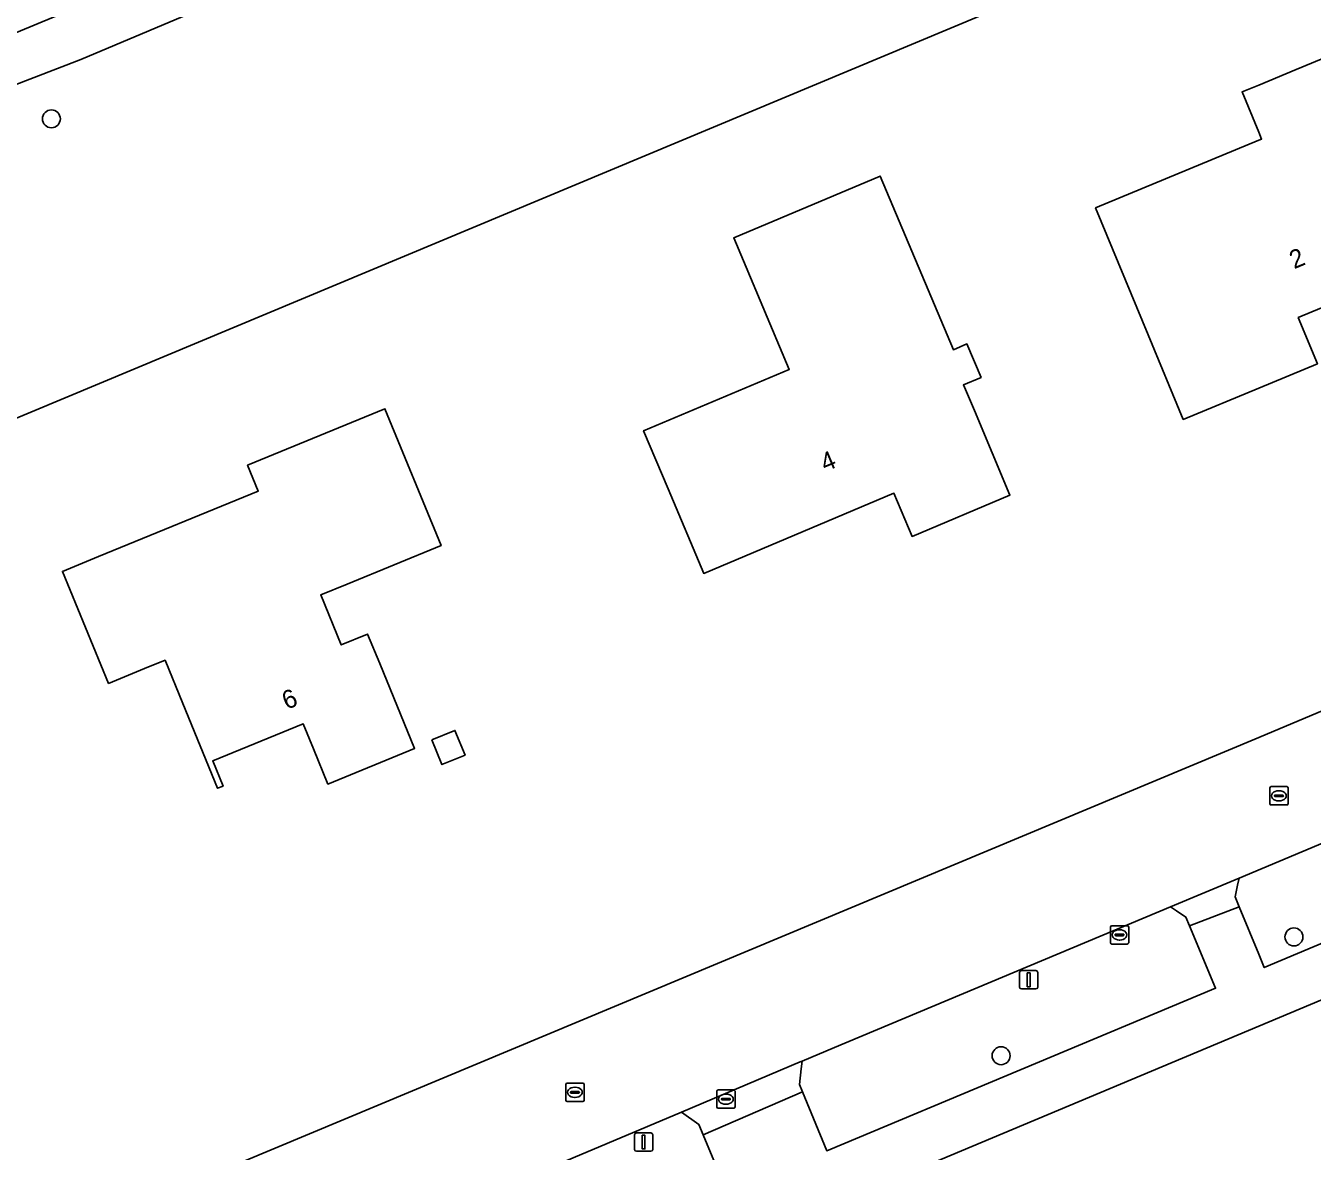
# Model space of a CAD drawing. Extents: x 162417 to 163722, y 384268 to 385417.
# Drawn here: x 163432.7 to 163502.9, y 385024.2 to 385085.6 of the extents above; entities that cross this region are included whole.
import ezdxf

# ---------------------------------------------------------------- set-up
doc = ezdxf.new("R2010")
doc.units = 0
for name, color, linetype in [('IMGEO_Berm_groen', 7, 'Continuous'), ('IMGEO_Boom', 7, 'Continuous'), ('IMGEO_Erf', 7, 'Continuous'), ('IMGEO_Groenvoorziening', 7, 'Continuous'), ('IMGEO_Kolk', 7, 'Continuous'), ('IMGEO_Lichtmast', 7, 'Continuous'), ('IMGEO_Loofbos', 7, 'Continuous'), ('IMGEO_Pand', 7, 'Continuous'), ('IMGEO_Pand_nummerreeks', 7, 'Continuous'), ('IMGEO_Rijbaan_lokaal_gesloten', 7, 'Continuous'), ('IMGEO_Rioolput', 7, 'Continuous'), ('IMGEO_Voetpad_halfverhard', 7, 'Continuous'), ('IMGEO_Voetpad_open', 7, 'Continuous')]:
    doc.layers.add(name, color=color, linetype=linetype)

msp = doc.modelspace()

# ---------------------------------------------------------------- linework, layer by layer
at = {"layer": 'IMGEO_Berm_groen'}
msp.add_lwpolyline([(163529.399, 385051.967), (163526.498, 385050.73), (163505.769, 385042.017), (163498.926, 385039.152), (163498.844, 385038.762), (163498.711, 385038.132), (163498.937, 385037.584), (163500, 385035.007), (163500.305, 385034.267), (163533.125, 385048.062)], dxfattribs=at)
for points in [[(163497.646, 385033.141), (163496.228, 385036.548), (163496.03, 385037.025), (163495.516, 385037.371), (163495.193, 385037.589), (163476.854, 385029.911), (163475.087, 385029.166), (163475.042, 385028.747), (163474.948, 385027.895), (163475.114, 385027.491), (163476.433, 385024.272)], [(163470.993, 385022.003), (163469.69, 385025.15), (163469.456, 385025.715), (163468.504, 385026.389), (163448.57, 385017.982), (163448.438, 385017.701), (163448.097, 385016.974), (163448.318, 385016.446), (163449.689, 385013.164)]]:
    msp.add_lwpolyline(points, close=True, dxfattribs=at)
at = {"layer": 'IMGEO_Boom'}
for centre in [(163434.132, 385080.566), (163501.923, 385035.94), (163485.947, 385029.459)]:
    msp.add_circle(centre, 0.489, dxfattribs=at)
at = {"layer": 'IMGEO_Erf'}
for points in [[(163526.981, 385058.237), (163524.402, 385063.53), (163507.868, 385095.856), (163500, 385092.556), (163419.878, 385059.084), (163371.144, 385038.583), (163343.981, 385026.826), (163354.406, 385000), (163357.745, 384991.405), (163359.186, 384987.697), (163387.545, 384999.704), (163388.243, 385000), (163425.932, 385015.904), (163500, 385046.827), (163524.917, 385057.312)], [(163500, 385082.41), (163502.045, 385083.258), (163506.663, 385085.173), (163511.47, 385073.585), (163502.16, 385069.723), (163503.203, 385067.206), (163500, 385065.878), (163495.882, 385064.17), (163493.966, 385068.789), (163491.098, 385075.704), (163500, 385079.397), (163500.156, 385079.461), (163500, 385079.838), (163499.09, 385082.032)], [(163467.782, 385060.378), (163466.445, 385063.55), (163474.386, 385066.897), (163471.362, 385074.072), (163479.351, 385077.439), (163483.342, 385067.971), (163484.082, 385068.283), (163484.851, 385066.459), (163483.894, 385066.055), (163484.488, 385064.647), (163486.43, 385060.039), (163481.092, 385057.789), (163480.099, 385060.143), (163469.725, 385055.77)], [(163450.264, 385055.186), (163448.83, 385054.597), (163449.95, 385051.868), (163451.384, 385052.457), (163452.045, 385050.847), (163453.944, 385046.221), (163449.215, 385044.28), (163448.429, 385046.195), (163447.867, 385047.564), (163442.937, 385045.541), (163443.499, 385044.172), (163443.203, 385044.05), (163441.304, 385048.676), (163440.337, 385051.032), (163439.221, 385050.574), (163437.248, 385049.764), (163434.737, 385055.88), (163436.71, 385056.69), (163445.416, 385060.263), (163444.837, 385061.673), (163452.327, 385064.748), (163455.389, 385057.29)], [(163454.889, 385046.683), (163456.147, 385047.2), (163456.699, 385045.856), (163455.441, 385045.34)]]:
    msp.add_lwpolyline(points, close=True, dxfattribs=at)
msp.add_lwpolyline([(163571.782, 384971.962), (163557.559, 385000), (163534.443, 385045.503), (163500, 385031.078), (163425.859, 385000), (163365.371, 384974.629), (163363.507, 384973.847), (163366.161, 384967.778), (163366.55, 384967.171), (163368.242, 384964.531)], dxfattribs=at)
at = {"layer": 'IMGEO_Groenvoorziening'}
msp.add_lwpolyline([(163481.985, 385145.032), (163480.053, 385147.889), (163478.195, 385150.521), (163474.918, 385154.813), (163471.459, 385158.99), (163429.736, 385126.498), (163414.218, 385078.468), (163428.256, 385083.644), (163444.192, 385090.257), (163456.158, 385095.426)], close=True, dxfattribs=at)
at = {"layer": 'IMGEO_Kolk'}
for p, q in [((163491.906, 385035.624), (163491.906, 385036.476)), ((163491.981, 385036.55), (163492.833, 385036.55)), ((163492.208, 385036.093), (163492.606, 385036.093)), ((163492.394, 385036.33), (163492.419, 385036.33)), ((163492.907, 385036.476), (163492.907, 385035.624)), ((163492.833, 385035.55), (163491.981, 385035.55)), ((163492.165, 385036.044), (163492.165, 385036.056)), ((163492.603, 385036.007), (163492.205, 385036.007)), ((163492.417, 385035.77), (163492.392, 385035.77)), ((163492.649, 385036.056), (163492.649, 385036.044)), ((163470.431, 385026.665), (163470.431, 385027.517)), ((163470.506, 385027.591), (163471.358, 385027.591)), ((163470.69, 385027.085), (163470.69, 385027.097)), ((163471.128, 385027.048), (163470.73, 385027.048)), ((163470.733, 385027.134), (163471.131, 385027.134)), ((163470.919, 385027.371), (163470.944, 385027.371)), ((163471.174, 385027.097), (163471.174, 385027.085)), ((163471.432, 385027.517), (163471.432, 385026.665)), ((163471.358, 385026.591), (163470.506, 385026.591)), ((163470.942, 385026.811), (163470.917, 385026.811))]:
    msp.add_line(p, q, dxfattribs=at)
for points in [[(163491.906, 385035.624), (163491.906, 385036.476)], [(163491.981, 385036.55), (163492.833, 385036.55)], [(163492.907, 385036.476), (163492.907, 385035.624)], [(163492.833, 385035.55), (163491.981, 385035.55)], [(163470.431, 385026.665), (163470.431, 385027.517)], [(163470.506, 385027.591), (163471.358, 385027.591)], [(163471.432, 385027.517), (163471.432, 385026.665)], [(163471.358, 385026.591), (163470.506, 385026.591)]]:
    msp.add_lwpolyline(points, dxfattribs=at)
for centre, radius, start, end in [((163491.983, 385036.474), 0.0765, 91.55205, 178.44795), ((163491.983, 385036.474), 0.0765, 91.55205, 178.44795), ((163492.205, 385036.053), 0.0403, 85.87752, 175.75265), ((163492.61, 385036.055), 0.0386, 1.73085, 96.63898), ((163492.831, 385036.474), 0.0765, 1.55205, 88.44795), ((163492.831, 385036.474), 0.0765, 1.55205, 88.44795), ((163491.983, 385035.626), 0.0765, 181.55205, 268.44795), ((163491.983, 385035.626), 0.0765, 181.55205, 268.44795), ((163492.202, 385036.043), 0.0366, 178.93798, 274.71019), ((163492.606, 385036.05), 0.043, 264.86636, 352.45326), ((163492.831, 385035.626), 0.0765, 271.55205, 358.44795), ((163492.831, 385035.626), 0.0765, 271.55205, 358.44795), ((163470.508, 385027.515), 0.0765, 91.55205, 178.44795), ((163470.508, 385027.515), 0.0765, 91.55205, 178.44795), ((163470.73, 385027.094), 0.0403, 85.87752, 175.75265), ((163470.727, 385027.084), 0.0366, 178.93798, 274.71019), ((163471.131, 385027.091), 0.043, 264.86636, 352.45326), ((163471.135, 385027.096), 0.0386, 1.73085, 96.63898), ((163471.356, 385027.515), 0.0765, 1.55205, 88.44795), ((163471.356, 385027.515), 0.0765, 1.55205, 88.44795), ((163470.508, 385026.667), 0.0765, 181.55205, 268.44795), ((163470.508, 385026.667), 0.0765, 181.55205, 268.44795), ((163471.356, 385026.667), 0.0765, 271.55205, 358.44795), ((163471.356, 385026.667), 0.0765, 271.55205, 358.44795)]:
    msp.add_arc(centre, radius, start, end, dxfattribs=at)
for centre, major_axis, ratio, start_param, end_param in [((163492.393, 385036.05), (-0.387, 0.002), 0.722429, 4.712389, 7.853982), ((163492.418, 385036.05), (-0.39, 0.002), 0.717154, 1.570796, 4.712389), ((163470.918, 385027.091), (-0.387, 0.002), 0.722429, 4.712389, 7.853982), ((163470.943, 385027.091), (-0.39, 0.002), 0.717154, 1.570796, 4.712389)]:
    msp.add_ellipse(centre, major_axis=major_axis, ratio=ratio, start_param=start_param, end_param=end_param, dxfattribs=at)
at = {"layer": 'IMGEO_Lichtmast'}
for p, q in [((163486.955, 385033.2), (163486.955, 385034)), ((163486.955, 385034), (163486.955, 385033.2)), ((163487.055, 385034.1), (163487.845, 385034.1)), ((163487.845, 385034.1), (163487.055, 385034.1)), ((163487.945, 385034), (163487.945, 385033.2)), ((163487.945, 385033.2), (163487.945, 385034)), ((163487.845, 385033.1), (163487.055, 385033.1)), ((163487.055, 385033.1), (163487.845, 385033.1)), ((163465.947, 385024.347), (163465.947, 385025.147)), ((163465.947, 385025.147), (163465.947, 385024.347)), ((163466.047, 385025.247), (163466.837, 385025.247)), ((163466.837, 385025.247), (163466.047, 385025.247)), ((163466.937, 385025.147), (163466.937, 385024.347)), ((163466.937, 385024.347), (163466.937, 385025.147)), ((163466.837, 385024.247), (163466.047, 385024.247)), ((163466.047, 385024.247), (163466.837, 385024.247))]:
    msp.add_line(p, q, dxfattribs=at)
for points in [[(163487.375, 385033.975), (163487.525, 385033.975), (163487.525, 385033.225), (163487.375, 385033.225), (163487.375, 385033.975)], [(163466.367, 385025.122), (163466.517, 385025.122), (163466.517, 385024.372), (163466.367, 385024.372), (163466.367, 385025.122)]]:
    msp.add_lwpolyline(points, dxfattribs=at)
for centre, start, end in [((163487.055, 385034), 90, 180), ((163487.055, 385034), 90, 180), ((163487.845, 385034), 0, 90), ((163487.845, 385034), 360, 90), ((163487.055, 385033.2), 180, 270), ((163487.055, 385033.2), 180, 270), ((163487.845, 385033.2), 270, 0), ((163487.845, 385033.2), 270, 0), ((163466.047, 385025.147), 90, 180), ((163466.047, 385025.147), 90, 180), ((163466.837, 385025.147), 0, 90), ((163466.837, 385025.147), 360, 90), ((163466.047, 385024.347), 180, 270), ((163466.047, 385024.347), 180, 270), ((163466.837, 385024.347), 270, 0), ((163466.837, 385024.347), 270, 0)]:
    msp.add_arc(centre, 0.1, start, end, dxfattribs=at)
at = {"layer": 'IMGEO_Loofbos'}
msp.add_lwpolyline([(163460.206, 385094.129), (163435.738, 385083.799), (163412.002, 385074.664), (163384.948, 385064.683), (163369.084, 385058.609), (163325.132, 385042.177), (163345.34, 385000), (163348.459, 384993.49), (163350.645, 384990.763), (163353.753, 384989.786), (163357.745, 384991.405), (163354.406, 385000), (163343.981, 385026.826), (163371.144, 385038.583), (163419.878, 385059.084), (163500, 385092.556)], dxfattribs=at)
at = {"layer": 'IMGEO_Pand'}
for points in [[(163500, 385082.41), (163499.09, 385082.032), (163500, 385079.838), (163500.156, 385079.461), (163500, 385079.397), (163491.098, 385075.704), (163493.966, 385068.789), (163495.882, 385064.17), (163500, 385065.878), (163503.203, 385067.206), (163502.16, 385069.723), (163511.47, 385073.585), (163506.663, 385085.173), (163502.045, 385083.258)], [(163467.782, 385060.378), (163469.725, 385055.77), (163480.099, 385060.143), (163481.092, 385057.789), (163486.43, 385060.039), (163484.488, 385064.647), (163483.894, 385066.055), (163484.851, 385066.459), (163484.082, 385068.283), (163483.342, 385067.971), (163479.351, 385077.439), (163471.362, 385074.072), (163474.386, 385066.897), (163466.445, 385063.55)], [(163450.264, 385055.186), (163455.389, 385057.29), (163452.327, 385064.748), (163444.837, 385061.673), (163445.416, 385060.263), (163436.71, 385056.69), (163434.737, 385055.88), (163437.248, 385049.764), (163439.221, 385050.574), (163440.337, 385051.032), (163441.304, 385048.676), (163443.203, 385044.05), (163443.499, 385044.172), (163442.937, 385045.541), (163447.867, 385047.564), (163448.429, 385046.195), (163449.215, 385044.28), (163453.944, 385046.221), (163452.045, 385050.847), (163451.384, 385052.457), (163449.95, 385051.868), (163448.83, 385054.597)], [(163454.889, 385046.683), (163455.441, 385045.34), (163456.699, 385045.856), (163456.147, 385047.2)]]:
    msp.add_lwpolyline(points, close=True, dxfattribs=at)
at = {"layer": 'IMGEO_Rijbaan_lokaal_gesloten'}
for points in [[(163527.71, 385058.563), (163526.981, 385058.237), (163524.917, 385057.312), (163500, 385046.827), (163425.932, 385015.904), (163388.243, 385000), (163387.545, 384999.704), (163359.186, 384987.697), (163354.083, 384985.536)], [(163468.504, 385026.389), (163474.991, 385029.126), (163475.087, 385029.166), (163476.854, 385029.911), (163495.193, 385037.589), (163498.926, 385039.152), (163505.769, 385042.017), (163526.498, 385050.73), (163529.399, 385051.967), (163530.708, 385052.491), (163530.635, 385052.693), (163532.866, 385053.668)], [(163357.313, 384979.632), (163357.952, 384979.9), (163390.13, 384993.491), (163390.981, 384993.848), (163394.735, 384995.421), (163395.6, 384995.783), (163411.617, 385002.494), (163413.331, 385003.218), (163421.331, 385006.599), (163421.429, 385006.64), (163429.137, 385009.898), (163441.213, 385014.921), (163448.57, 385017.982), (163468.504, 385026.389)]]:
    msp.add_lwpolyline(points, dxfattribs=at)
at = {"layer": 'IMGEO_Rioolput'}
for p, q in [((163500.602, 385043.21), (163500.602, 385044.062)), ((163500.677, 385044.136), (163501.529, 385044.136)), ((163501.09, 385043.916), (163501.115, 385043.916)), ((163501.603, 385044.062), (163501.603, 385043.21)), ((163501.529, 385043.136), (163500.677, 385043.136)), ((163500.861, 385043.63), (163500.861, 385043.642)), ((163501.299, 385043.593), (163500.901, 385043.593)), ((163500.904, 385043.679), (163501.302, 385043.679)), ((163501.113, 385043.356), (163501.088, 385043.356)), ((163501.345, 385043.642), (163501.345, 385043.63)), ((163462.195, 385027.038), (163462.195, 385027.89)), ((163462.27, 385027.964), (163463.122, 385027.964)), ((163462.683, 385027.744), (163462.708, 385027.744)), ((163463.196, 385027.89), (163463.196, 385027.038)), ((163463.122, 385026.964), (163462.27, 385026.964)), ((163462.454, 385027.458), (163462.454, 385027.47)), ((163462.892, 385027.421), (163462.494, 385027.421)), ((163462.497, 385027.507), (163462.895, 385027.507)), ((163462.706, 385027.184), (163462.681, 385027.184)), ((163462.938, 385027.47), (163462.938, 385027.458))]:
    msp.add_line(p, q, dxfattribs=at)
for points in [[(163500.602, 385043.21), (163500.602, 385044.062)], [(163500.677, 385044.136), (163501.529, 385044.136)], [(163501.603, 385044.062), (163501.603, 385043.21)], [(163501.529, 385043.136), (163500.677, 385043.136)], [(163462.195, 385027.038), (163462.195, 385027.89)], [(163462.27, 385027.964), (163463.122, 385027.964)], [(163463.196, 385027.89), (163463.196, 385027.038)], [(163463.122, 385026.964), (163462.27, 385026.964)]]:
    msp.add_lwpolyline(points, dxfattribs=at)
for centre, radius, start, end in [((163500.679, 385044.06), 0.0765, 91.55205, 178.44795), ((163500.679, 385044.06), 0.0765, 91.55205, 178.44795), ((163501.527, 385044.06), 0.0765, 1.55205, 88.44795), ((163501.527, 385044.06), 0.0765, 1.55205, 88.44795), ((163500.679, 385043.212), 0.0765, 181.55205, 268.44795), ((163500.679, 385043.212), 0.0765, 181.55205, 268.44795), ((163500.901, 385043.639), 0.0403, 85.87752, 175.75265), ((163500.898, 385043.629), 0.0366, 178.93798, 274.71019), ((163501.302, 385043.636), 0.043, 264.86636, 352.45326), ((163501.306, 385043.641), 0.0386, 1.73085, 96.63898), ((163501.527, 385043.212), 0.0765, 271.55205, 358.44795), ((163501.527, 385043.212), 0.0765, 271.55205, 358.44795), ((163462.272, 385027.888), 0.0765, 91.55205, 178.44795), ((163462.272, 385027.888), 0.0765, 91.55205, 178.44795), ((163463.12, 385027.888), 0.0765, 1.55205, 88.44795), ((163463.12, 385027.888), 0.0765, 1.55205, 88.44795), ((163462.272, 385027.04), 0.0765, 181.55205, 268.44795), ((163462.272, 385027.04), 0.0765, 181.55205, 268.44795), ((163462.494, 385027.467), 0.0403, 85.87752, 175.75265), ((163462.491, 385027.457), 0.0366, 178.93798, 274.71019), ((163462.895, 385027.464), 0.043, 264.86636, 352.45326), ((163462.899, 385027.469), 0.0386, 1.73085, 96.63898), ((163463.12, 385027.04), 0.0765, 271.55205, 358.44795), ((163463.12, 385027.04), 0.0765, 271.55205, 358.44795)]:
    msp.add_arc(centre, radius, start, end, dxfattribs=at)
for centre, major_axis, ratio, start_param, end_param in [((163501.089, 385043.636), (-0.387, 0.002), 0.722429, 4.712389, 7.853982), ((163501.114, 385043.636), (-0.39, 0.002), 0.717154, 1.570796, 4.712389), ((163462.682, 385027.464), (-0.387, 0.002), 0.722429, 4.712389, 7.853982), ((163462.707, 385027.464), (-0.39, 0.002), 0.717154, 1.570796, 4.712389)]:
    msp.add_ellipse(centre, major_axis=major_axis, ratio=ratio, start_param=start_param, end_param=end_param, dxfattribs=at)
at = {"layer": 'IMGEO_Voetpad_halfverhard'}
msp.add_lwpolyline([(163369.084, 385058.609), (163384.948, 385064.683), (163412.002, 385074.664), (163435.738, 385083.799), (163460.206, 385094.129), (163492.294, 385108.073), (163500, 385111.293), (163500.985, 385111.712), (163499.639, 385114.264), (163498.641, 385113.666), (163492.495, 385111.122), (163456.158, 385095.426), (163444.192, 385090.257), (163428.256, 385083.644), (163414.218, 385078.468), (163411.269, 385077.22), (163320.189, 385043.176), (163319.914, 385043.073), (163321.067, 385040.629), (163321.352, 385040.764), (163325.132, 385042.177)], close=True, dxfattribs=at)
at = {"layer": 'IMGEO_Voetpad_open'}
msp.add_lwpolyline([(163425.859, 385000), (163500, 385031.078), (163534.443, 385045.503), (163533.125, 385048.062), (163500.305, 385034.267), (163500, 385035.007), (163498.937, 385037.584), (163496.228, 385036.548), (163497.646, 385033.141), (163476.433, 385024.272), (163475.114, 385027.491), (163469.69, 385025.15), (163470.993, 385022.003), (163449.689, 385013.164), (163448.318, 385016.446), (163447.247, 385015.982), (163442.302, 385013.957), (163443.689, 385010.64), (163422.621, 385001.771)], dxfattribs=at)
for points in [[(163498.937, 385037.584), (163498.711, 385038.132), (163498.844, 385038.762), (163498.926, 385039.152), (163495.193, 385037.589), (163495.516, 385037.371), (163496.03, 385037.025), (163496.228, 385036.548)], [(163475.114, 385027.491), (163474.948, 385027.895), (163475.042, 385028.747), (163475.087, 385029.166), (163474.991, 385029.126), (163468.504, 385026.389), (163469.456, 385025.715), (163469.69, 385025.15)]]:
    msp.add_lwpolyline(points, close=True, dxfattribs=at)

# ---------------------------------------------------------------- texts
at = {"layer": 'IMGEO_Pand_nummerreeks'}
for s, rotation, p in [('2', 22.52979, (163501.933, 385072.356)), ('4', 22.85711, (163476.349, 385061.297)), ('6', 22.31671, (163446.968, 385048.32))]:
    msp.add_text(s, height=1, rotation=rotation, dxfattribs=at).set_placement(p)

doc.saveas('drawing.dxf')
